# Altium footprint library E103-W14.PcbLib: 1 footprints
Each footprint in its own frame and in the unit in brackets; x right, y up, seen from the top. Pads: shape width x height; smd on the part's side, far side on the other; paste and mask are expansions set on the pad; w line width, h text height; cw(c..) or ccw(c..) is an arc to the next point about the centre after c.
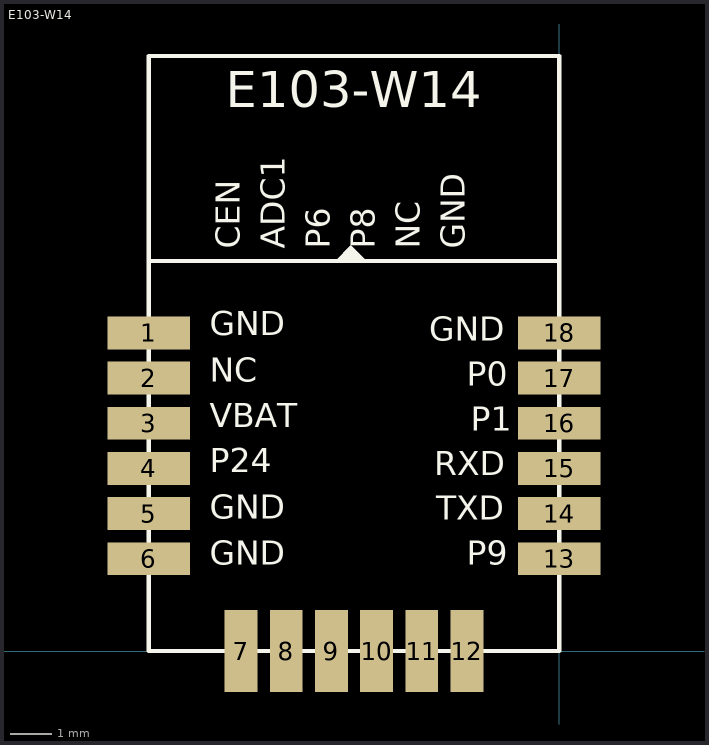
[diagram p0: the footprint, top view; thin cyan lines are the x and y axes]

## E103-W14 [mm]
pads (18):
  rect 2x0.8 smd: 1(-10,7.75) 2(-10,6.65) 3(-10,5.55) 4(-10,4.45) 5(-10,3.35) 6(-10,2.25) 13(0,2.25) 14(0,3.35) 15(0,4.45) 16(0,5.55) 17(0,6.65) 18(0,7.75)
  rect 0.8x2 smd: 7(-7.75,0) 8(-6.65,0) 9(-5.55,0) 10(-4.45,0) 11(-3.35,0) 12(-2.25,0)
Top Overlay:
  region: -5.461,9.5 -5.08,9.881 -4.728,9.529
  lines w0.1: -10,9.5 0,9.5 ; -10,0 -10,14.5 0,14.5 0,0 -10,0
  text "NC" at -8.509,6.367 h1
  text "GND" at -8.509,1.905 h1
  text "GND" at -3.169,7.366 h1
  text "P0" at -2.254,6.266 h1
  text "RXD" at -3.048,4.091 h1
  text "TXD" at -2.993,3.005 h1
  text "VBAT" at -8.509,5.263 h1
  text "P24" at -8.509,4.157 h1
  text "GND" at -8.509,3.031 h1
  text "CEN" at -7.585,9.795 h1
  text "ADC1" at -6.489,9.795 h1
  text "P6" at -5.394,9.795 h1
  text "P8" at -4.298,9.795 h1
  text "NC" at -3.203,9.795 h1
  text "GND" at -2.107,9.795 h1
  text "P1" at -2.153,5.178 h1
  text "E103-W14" at -8.128,12.954 h1.5
  text "GND" at -8.509,7.493 h1
  text "P9" at -2.257,1.905 h1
